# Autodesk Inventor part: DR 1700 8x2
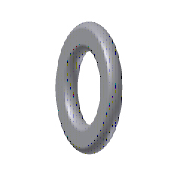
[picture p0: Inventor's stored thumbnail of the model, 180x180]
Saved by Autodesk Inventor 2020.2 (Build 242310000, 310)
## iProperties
Manager: www.cadconsulting.pl
Company: Fabian Stasiak CAD Consulting
IsCustomPart: 1
Created: 2014-02
Part Number: DR 1700 8x2
Material: ABS-DFA-R
Description: O Ring
Document SubType Name: Modeling
Designer: F.Stasiak
Standard Revision: 1
Manufacturer: DME
Language: pl-PL
Size Designation: 8x2
Categories: <MemberInstance><Categories><Category DisplayName="Forma wtryskowa" InternalName="349578f2-f4d4-4954-8c09-8e99297a61c0" Mnemonic="MOLD"><Category DisplayName="K
Density: 1.04 g/cm^3
Appearance: Domyślna
Catalog Web Link: www.expertbooks.pl
Author: F.Stasiak
Subject: Zbiór ćwiczeń. Autodesk Inventor 2020. Kurs Professional
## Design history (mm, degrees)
sketch "Sketch1"
  geometry: L1 (0, -1.4)-(0, 1.4) reference; L2 (-1, 0)-(6, 0) reference; L3 (5.6, -0.8)-(4.4, -0.8); L4 (4.4, 0.8)-(5.6, 0.8); A1 r 1 centre (5, 0) between (4.4, 0.8) and (4.4, -0.8); A2 r 1 centre (5, 0) between (5.6, 0.8) and (4.4, 0.8); A3 r 1 centre (5, 0) between (5.6, -0.8) and (5.6, 0.8); A4 r 1 centre (5, 0) between (4.4, -0.8) and (5.6, -0.8); 1 further point
  constraints: 8 point on circle, 4 centre point, 4 end point, 3 parallel, 1 point on line
  dimensions: "d3" = 10 diameter of A1.centre L1 (= dx + d2); "d9" = 2 diameter of A1 (= d2); "d20" = 1.6 distance between parallel lines of L3 L4 (= t_CS)
revolve "Revolution1" sketch "Sketch1" stored, may be unused: angle "d24" = 90 deg
sketch "Sketch2"
  geometry: L1 (-6.645, 0)-(7.668, 0) reference; L2 (0, -1.128)-(0, 1.166) reference; L3 (-5.6, 0.8)-(5.6, 0.8) reference; L4 (-5.6, -0.8)-(5.6, -0.8) reference; L5 (3.377, 0.8)-(6.623, 0.8); L6 (6.424, 0.617)-(6.3, -0.8); L7 (3.7, -0.8)-(6.3, -0.8); L8 (3.576, 0.617)-(3.7, -0.8); L9 (3.7, -0.8)-(3.7, 0.8); L10 (6.3, -0.8)-(6.3, 0.8); A1 r 1 centre (5, 0) between (5.6, -0.8) and (5.6, 0.8) reference; A2 r 0.2 centre (6.623, 0.6) between (6.623, 0.8) and (6.424, 0.617); A3 r 0.2 centre (3.377, 0.6) between (3.576, 0.617) and (3.377, 0.8); 1 further point
  constraints: 12 end point, 5 point on line, 4 point on circle, 4 tangent, 2 centre point, 2 perpendicular, 1 midpoint, 1 parallel, 1 vertical alignment
  dimensions: "d13" = 0.2 radius of A2 (= d100); "d14" = 0.2 radius of A3 (= d13); "d15" = 5 deg angle of L8 L9 (= d101); "d16" = 5 deg angle of L6 L10 (= d15); "d17" = 2.6 distance of L7.start L6.end (= b_CS)
feature "RevolutionSrf1" sketch "Sketch2" dims angle "d18" = 90 deg
fillet "Fillet1" dims "d19" = 0.3 (= r)
fillet "Fillet2" dims "d23" = 0.3
body "Solid1"
body "Srf1"
other parameters: "dx" = 8 [user parameter; used in 1 equation term], "d2" = 2 [user parameter; used in 2 equation terms], "b_CS" = 2.6 [user parameter; used in 1 equation term], "t_CS" = 1.6 [user parameter; used in 1 equation term], "d21" = 0, "d22" = 0, "r" = 0.3 [user parameter; used in 1 equation term], "d100" = 0.2 [user parameter; used in 1 equation term], "d101" = 5 deg [user parameter; used in 1 equation term]
